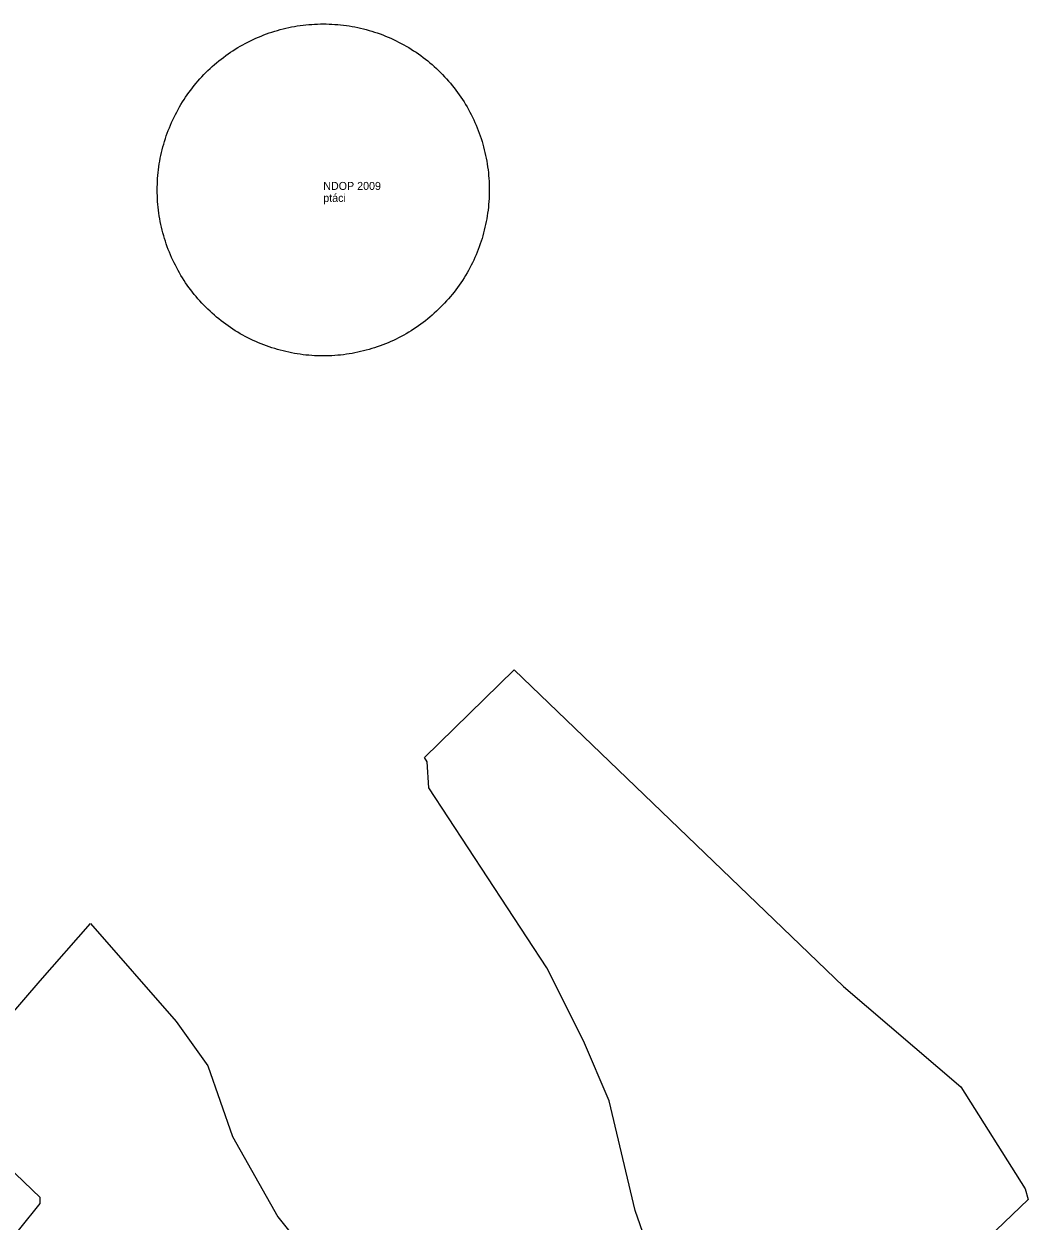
# Model space of a CAD drawing. Extents: x -477403 to -465463, y -1159182 to -1149227.
# Drawn here: x -474276.3 to -474025.3, y -1155401.8 to -1155102.5 of the extents above; entities that cross this region are included whole.
import ezdxf

# ---------------------------------------------------------------- set-up
doc = ezdxf.new("R2010")
doc.units = 0
for name, color, linetype in [('Vrstva 1', 7, 'Continuous'), ('Vrstva 10_stav', 7, 'Continuous'), ('Vrstva 2', 7, 'Continuous')]:
    doc.layers.add(name, color=color, linetype=linetype)

msp = doc.modelspace()

# ---------------------------------------------------------------- linework, layer by layer
at = {"layer": 'Vrstva 10_stav'}
for points in [[(-474240.506, -1155129.837), (-474240.252, -1155129.159), (-474239.987, -1155128.485), (-474239.71, -1155127.816), (-474239.421, -1155127.152), (-474239.12, -1155126.493), (-474238.809, -1155125.84), (-474238.486, -1155125.191), (-474238.151, -1155124.549), (-474237.806, -1155123.913), (-474237.449, -1155123.282), (-474237.081, -1155122.658), (-474236.703, -1155122.041), (-474236.314, -1155121.43), (-474235.914, -1155120.826), (-474235.504, -1155120.23), (-474235.083, -1155119.64), (-474234.653, -1155119.058), (-474234.212, -1155118.483), (-474233.761, -1155117.916), (-474233.301, -1155117.358), (-474232.83, -1155116.807), (-474232.35, -1155116.264), (-474231.861, -1155115.731), (-474231.363, -1155115.205), (-474230.855, -1155114.689), (-474230.338, -1155114.181), (-474229.813, -1155113.683), (-474229.279, -1155113.193), (-474228.737, -1155112.714), (-474228.186, -1155112.243), (-474227.627, -1155111.783), (-474227.061, -1155111.332), (-474226.486, -1155110.891), (-474225.904, -1155110.46), (-474225.314, -1155110.04), (-474224.717, -1155109.63), (-474224.114, -1155109.23), (-474223.503, -1155108.841), (-474222.885, -1155108.462), (-474222.261, -1155108.095), (-474221.631, -1155107.738), (-474220.995, -1155107.392), (-474220.352, -1155107.058), (-474219.704, -1155106.735), (-474219.051, -1155106.423), (-474218.391, -1155106.123), (-474217.727, -1155105.834), (-474217.058, -1155105.557), (-474216.385, -1155105.292), (-474215.706, -1155105.038), (-474215.024, -1155104.796), (-474214.337, -1155104.566), (-474213.646, -1155104.349), (-474212.952, -1155104.143), (-474212.254, -1155103.95), (-474211.553, -1155103.768), (-474210.849, -1155103.599), (-474210.142, -1155103.442), (-474209.432, -1155103.298), (-474208.72, -1155103.166), (-474208.006, -1155103.046), (-474207.289, -1155102.939), (-474206.572, -1155102.845), (-474205.852, -1155102.763), (-474205.131, -1155102.693), (-474204.409, -1155102.637), (-474203.686, -1155102.592), (-474202.963, -1155102.561), (-474202.239, -1155102.542), (-474201.515, -1155102.536), (-474200.79, -1155102.542), (-474200.067, -1155102.561), (-474199.343, -1155102.592), (-474198.62, -1155102.637), (-474197.898, -1155102.693), (-474197.177, -1155102.763), (-474196.458, -1155102.845), (-474195.74, -1155102.939), (-474195.024, -1155103.046), (-474194.309, -1155103.166), (-474193.597, -1155103.298), (-474192.888, -1155103.442), (-474192.181, -1155103.599), (-474191.477, -1155103.768), (-474190.775, -1155103.95), (-474190.078, -1155104.143), (-474189.383, -1155104.349), (-474188.693, -1155104.566), (-474188.006, -1155104.796), (-474187.323, -1155105.038), (-474186.645, -1155105.292), (-474185.971, -1155105.557), (-474185.302, -1155105.834), (-474184.638, -1155106.123), (-474183.979, -1155106.423), (-474183.325, -1155106.735), (-474182.677, -1155107.058), (-474182.035, -1155107.392), (-474181.398, -1155107.738), (-474180.768, -1155108.095)], [(-474180.768, -1155108.095), (-474180.144, -1155108.462), (-474179.527, -1155108.841), (-474178.916, -1155109.23), (-474178.312, -1155109.63), (-474177.715, -1155110.04), (-474177.125, -1155110.46), (-474176.543, -1155110.891), (-474175.969, -1155111.332), (-474175.402, -1155111.783), (-474174.843, -1155112.243), (-474174.293, -1155112.714), (-474173.75, -1155113.193), (-474173.216, -1155113.683), (-474172.691, -1155114.181), (-474172.175, -1155114.689), (-474171.667, -1155115.205), (-474171.168, -1155115.731), (-474170.679, -1155116.264), (-474170.199, -1155116.807), (-474169.729, -1155117.358), (-474169.268, -1155117.916), (-474168.818, -1155118.483), (-474168.377, -1155119.058), (-474167.946, -1155119.64), (-474167.525, -1155120.23), (-474167.115, -1155120.826), (-474166.715, -1155121.43), (-474166.326, -1155122.041), (-474165.948, -1155122.658), (-474165.58, -1155123.282), (-474165.224, -1155123.913), (-474164.878, -1155124.549), (-474164.544, -1155125.191), (-474164.221, -1155125.84), (-474163.909, -1155126.493), (-474163.609, -1155127.152), (-474163.32, -1155127.816), (-474163.043, -1155128.485), (-474162.777, -1155129.159), (-474162.524, -1155129.837), (-474162.282, -1155130.52), (-474162.052, -1155131.207), (-474161.834, -1155131.898), (-474161.629, -1155132.592), (-474161.435, -1155133.29), (-474161.254, -1155133.991), (-474161.085, -1155134.695), (-474160.928, -1155135.402), (-474160.784, -1155136.112), (-474160.652, -1155136.824), (-474160.532, -1155137.538), (-474160.425, -1155138.254), (-474160.331, -1155138.972), (-474160.249, -1155139.692), (-474160.179, -1155140.413), (-474160.123, -1155141.135), (-474160.078, -1155141.857), (-474160.047, -1155142.581), (-474160.028, -1155143.305), (-474160.021, -1155144.029)], [(-474208.72, -1155184.892), (-474209.432, -1155184.76), (-474210.142, -1155184.616), (-474210.849, -1155184.459), (-474211.553, -1155184.29), (-474212.254, -1155184.109), (-474212.952, -1155183.915), (-474213.646, -1155183.709), (-474214.337, -1155183.492), (-474215.024, -1155183.262), (-474215.706, -1155183.02), (-474216.385, -1155182.766), (-474217.058, -1155182.501), (-474217.727, -1155182.224), (-474218.391, -1155181.935), (-474219.051, -1155181.635), (-474219.704, -1155181.323), (-474220.352, -1155181), (-474220.995, -1155180.666), (-474221.631, -1155180.32), (-474222.261, -1155179.963), (-474222.885, -1155179.596), (-474223.503, -1155179.217), (-474224.114, -1155178.828), (-474224.717, -1155178.428), (-474225.314, -1155178.018), (-474225.904, -1155177.598), (-474226.486, -1155177.167), (-474227.061, -1155176.726), (-474227.627, -1155176.275), (-474228.186, -1155175.815), (-474228.737, -1155175.344), (-474229.279, -1155174.865), (-474229.813, -1155174.375), (-474230.338, -1155173.877), (-474230.855, -1155173.369), (-474231.363, -1155172.853), (-474231.861, -1155172.327), (-474232.35, -1155171.794), (-474232.83, -1155171.251), (-474233.301, -1155170.7), (-474233.761, -1155170.142), (-474234.212, -1155169.575), (-474234.653, -1155169), (-474235.083, -1155168.418), (-474235.504, -1155167.829), (-474235.914, -1155167.232), (-474236.314, -1155166.628), (-474236.703, -1155166.017), (-474237.081, -1155165.4), (-474237.449, -1155164.776), (-474237.806, -1155164.146), (-474238.151, -1155163.509), (-474238.486, -1155162.867), (-474238.809, -1155162.218), (-474239.12, -1155161.565), (-474239.421, -1155160.906), (-474239.71, -1155160.242), (-474239.987, -1155159.573), (-474240.252, -1155158.899), (-474240.506, -1155158.221), (-474240.747, -1155157.538), (-474240.977, -1155156.851), (-474241.195, -1155156.16), (-474241.401, -1155155.466), (-474241.594, -1155154.768), (-474241.776, -1155154.067), (-474241.945, -1155153.363), (-474242.101, -1155152.656), (-474242.246, -1155151.946), (-474242.378, -1155151.234), (-474242.497, -1155150.52), (-474242.604, -1155149.804), (-474242.699, -1155149.086), (-474242.781, -1155148.366), (-474242.85, -1155147.645), (-474242.907, -1155146.923), (-474242.951, -1155146.201), (-474242.983, -1155145.477), (-474243.002, -1155144.753), (-474243.008, -1155144.029), (-474243.002, -1155143.305), (-474242.983, -1155142.581), (-474242.951, -1155141.857), (-474242.907, -1155141.135), (-474242.85, -1155140.413), (-474242.781, -1155139.692), (-474242.699, -1155138.972), (-474242.604, -1155138.254), (-474242.497, -1155137.538), (-474242.378, -1155136.824), (-474242.246, -1155136.112), (-474242.101, -1155135.402), (-474241.945, -1155134.695), (-474241.776, -1155133.991), (-474241.594, -1155133.29), (-474241.401, -1155132.592), (-474241.195, -1155131.898), (-474240.977, -1155131.207), (-474240.747, -1155130.52), (-474240.506, -1155129.837)], [(-474160.021, -1155144.029), (-474160.028, -1155144.753), (-474160.047, -1155145.477), (-474160.078, -1155146.201), (-474160.123, -1155146.923), (-474160.179, -1155147.645), (-474160.249, -1155148.366), (-474160.331, -1155149.086), (-474160.425, -1155149.804), (-474160.532, -1155150.52), (-474160.652, -1155151.234), (-474160.784, -1155151.946), (-474160.928, -1155152.656), (-474161.085, -1155153.363), (-474161.254, -1155154.067), (-474161.435, -1155154.768), (-474161.629, -1155155.466), (-474161.834, -1155156.16), (-474162.052, -1155156.851), (-474162.282, -1155157.538), (-474162.524, -1155158.221), (-474162.777, -1155158.899), (-474163.043, -1155159.573), (-474163.32, -1155160.242), (-474163.609, -1155160.906), (-474163.909, -1155161.565), (-474164.221, -1155162.218), (-474164.544, -1155162.867), (-474164.878, -1155163.509), (-474165.224, -1155164.146), (-474165.58, -1155164.776), (-474165.948, -1155165.4), (-474166.326, -1155166.017), (-474166.715, -1155166.628), (-474167.115, -1155167.232), (-474167.525, -1155167.829), (-474167.946, -1155168.418), (-474168.377, -1155169), (-474168.818, -1155169.575), (-474169.268, -1155170.142), (-474169.729, -1155170.7), (-474170.199, -1155171.251), (-474170.679, -1155171.794), (-474171.168, -1155172.327), (-474171.667, -1155172.853), (-474172.175, -1155173.369), (-474172.691, -1155173.877), (-474173.216, -1155174.375), (-474173.75, -1155174.865), (-474174.293, -1155175.344), (-474174.843, -1155175.815), (-474175.402, -1155176.275), (-474175.969, -1155176.726), (-474176.543, -1155177.167), (-474177.125, -1155177.598), (-474177.715, -1155178.018), (-474178.312, -1155178.428), (-474178.916, -1155178.828), (-474179.527, -1155179.217), (-474180.144, -1155179.596), (-474180.768, -1155179.963), (-474181.398, -1155180.32), (-474182.035, -1155180.666), (-474182.677, -1155181), (-474183.325, -1155181.323), (-474183.979, -1155181.635), (-474184.638, -1155181.935), (-474185.302, -1155182.224), (-474185.971, -1155182.501), (-474186.645, -1155182.766), (-474187.323, -1155183.02), (-474188.006, -1155183.262), (-474188.693, -1155183.492), (-474189.383, -1155183.709), (-474190.078, -1155183.915), (-474190.775, -1155184.109), (-474191.477, -1155184.29), (-474192.181, -1155184.459), (-474192.888, -1155184.616), (-474193.597, -1155184.76), (-474194.309, -1155184.892), (-474195.024, -1155185.012), (-474195.74, -1155185.119), (-474196.458, -1155185.213), (-474197.177, -1155185.295), (-474197.898, -1155185.365), (-474198.62, -1155185.421), (-474199.343, -1155185.466), (-474200.067, -1155185.497), (-474200.79, -1155185.516), (-474201.515, -1155185.522), (-474202.239, -1155185.516), (-474202.963, -1155185.497), (-474203.686, -1155185.466), (-474204.409, -1155185.421), (-474205.131, -1155185.365), (-474205.852, -1155185.295), (-474206.572, -1155185.213), (-474207.289, -1155185.119), (-474208.006, -1155185.012), (-474208.72, -1155184.892)], [(-474176.219, -1155285.875), (-474153.812, -1155264), (-474071.438, -1155343.125), (-474042.156, -1155368.25), (-474026.031, -1155393.75), (-474025.344, -1155396.375), (-474043.375, -1155413.75)], [(-474112.406, -1155431.125), (-474123.531, -1155399.125), (-474130.062, -1155371.75), (-474136.469, -1155356.75), (-474145.625, -1155338.5), (-474175.125, -1155293.5), (-474175.531, -1155287), (-474176.219, -1155285.875)], [(-474287.625, -1155416.375), (-474272.312, -1155397.375), (-474272.312, -1155395.875), (-474282.688, -1155386), (-474296.688, -1155375.125), (-474296.375, -1155369.625), (-474272.25, -1155341.75), (-474259.688, -1155327.375), (-474238.25, -1155351.875), (-474230.344, -1155363), (-474224.219, -1155380.625), (-474212.875, -1155400.75), (-474208.844, -1155405.75)]]:
    msp.add_lwpolyline(points, dxfattribs=at)

# ---------------------------------------------------------------- texts
at = {"layer": 'Vrstva 1'}
msp.add_text('ptáci', height=2, dxfattribs=at).set_placement((-474201.514, -1155147.029))
msp.add_text('ptáci', height=2, dxfattribs=at).set_placement((-474201.514, -1155147.029))
at = {"layer": 'Vrstva 2'}
msp.add_text('NDOP 2009', height=2, dxfattribs=at).set_placement((-474201.514, -1155144.029))
msp.add_text('NDOP 2009', height=2, dxfattribs=at).set_placement((-474201.514, -1155144.029))

doc.saveas('drawing.dxf')
